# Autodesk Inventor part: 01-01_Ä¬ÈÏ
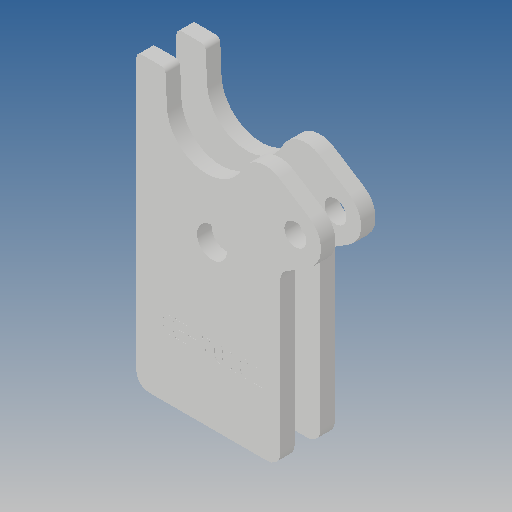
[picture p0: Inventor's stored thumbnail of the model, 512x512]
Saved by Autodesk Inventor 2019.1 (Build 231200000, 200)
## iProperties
Created: 2010-06
Part Number: 01-01_Ä¬ÈÏ
Material: Ogólny
Document SubType Name: Modeling
Designer: CADENGINEERING4
Density: 1 g/cm^3
Appearance: Domyślna
Author: CADENGINEERING4
Revision Number: ÈÎºÎ
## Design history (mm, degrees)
feature "NONE"
feature "NONE:1"
node "Bryła1"
node "Bryła2"
